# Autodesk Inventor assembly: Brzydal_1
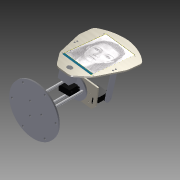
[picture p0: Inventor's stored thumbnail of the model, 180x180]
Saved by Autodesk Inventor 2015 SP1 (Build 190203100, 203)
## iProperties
Created: 2016-02
Part Number: Brzydal_1
Document SubType Name: Assembly
Designer: Rafał
Author: Rafał
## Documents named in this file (12)
- D:\Dropbox\Brzydal\Mechanika\Brzydal_1.iam
- D:\Dropbox\Brzydal\Mechanika\MG996R.ipt
- D:\Dropbox\Brzydal\Mechanika\orczyk_okragly.ipt
- D:\Dropbox\Brzydal\Mechanika\sruba_2_5.ipt
- D:\Dropbox\Brzydal\Mechanika\talerz.ipt
- D:\Dropbox\Brzydal\Mechanika\mocowanie_twarzy.ipt
- D:\Dropbox\Brzydal\Mechanika\twarz.ipt
- D:\Dropbox\Brzydal\Mechanika\podstawka dolna.ipt
- D:\Dropbox\Brzydal\Mechanika\sruba_80.ipt
- D:\Dropbox\Brzydal\Mechanika\twarz_ekran.ipt
- D:\Dropbox\Brzydal\Mechanika\sam_dol.ipt
- D:\Dropbox\Brzydal\Mechanika\kamera.ipt
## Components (29 placed, 11 different names)
1. MG996R:1 — Insert:5, Mate:21, Mate:22, Mate:23
2. orczyk_okragly:1 — Insert:5, Insert:6, Insert:7, Insert:8, Insert:9, Rotational:3
3. sruba_2_5:1 — Insert:8
4. sruba_2_5:2 — Insert:9
5. sruba_2_5:3 — Insert:7
6. sruba_2_5:4 — Insert:6
7. MG996R:2 — Insert:11, Mate:24, Mate:25, Mate:26
8. MG996R:3 — Insert:10, Mate:27, Mate:28, Mate:29
9. orczyk_okragly:2 — Insert:10, Insert:14, Insert:15, Insert:16, Insert:17, Rotational:1
10. orczyk_okragly:3 — Insert:11, Insert:12, Insert:13, Insert:18, Insert:19, Rotational:2
11. sruba_2_5:5 — Insert:15
12. sruba_2_5:6 — Insert:12
13. sruba_2_5:7 — Insert:14
14. sruba_2_5:8 — Insert:13
15. sruba_2_5:9 — Insert:17
16. sruba_2_5:10 — Insert:18
17. sruba_2_5:11 — Insert:19
18. sruba_2_5:12 — Insert:16
19. mocowanie_twarzy:1 — Rotational:2, Mate:19, Mate:20, Flush:3
20. mocowanie_twarzy:2 — Rotational:1, Flush:4
21. twarz:1 — Mate:19, Mate:20, Flush:3, Flush:4, Mate:30, Mate:31, Flush:5, Rotational:4
22. talerz:1 — Rotational:3, Mate:24, Mate:25, Mate:26, Mate:27, Mate:28, Mate:29
23. podstawka dolna:1 — Mate:21, Mate:22, Mate:23, Insert:20, Insert:21, Insert:22
24. sruba_80:1 — Insert:21
25. sruba_80:2 — Insert:20, Insert:23
26. sruba_80:3 — Insert:22
27. twarz_ekran:1 — Mate:30, Mate:31, Flush:5
28. sam_dol:1 — Insert:23
29. kamera:1 — Rotational:4
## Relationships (39: Insert 19, Mate 13, RevoluteJoint 4, Flush 3)
- Insert:5: MG996R:1 ↔ orczyk_okragly:1
- Insert:6: orczyk_okragly:1 ↔ sruba_2_5:4
- Insert:7: orczyk_okragly:1 ↔ sruba_2_5:3
- Insert:8: orczyk_okragly:1 ↔ sruba_2_5:1
- Insert:9: orczyk_okragly:1 ↔ sruba_2_5:2
- Insert:10: MG996R:3 ↔ orczyk_okragly:2
- Insert:11: MG996R:2 ↔ orczyk_okragly:3
- Insert:12: orczyk_okragly:3 ↔ sruba_2_5:6
- Insert:13: orczyk_okragly:3 ↔ sruba_2_5:8
- Insert:14: orczyk_okragly:2 ↔ sruba_2_5:7
- Insert:15: orczyk_okragly:2 ↔ sruba_2_5:5
- Insert:16: orczyk_okragly:2 ↔ sruba_2_5:12
- Insert:17: orczyk_okragly:2 ↔ sruba_2_5:9
- Insert:18: orczyk_okragly:3 ↔ sruba_2_5:10
- Insert:19: orczyk_okragly:3 ↔ sruba_2_5:11
- Rotational:1 [RevoluteJoint]: orczyk_okragly:2 ↔ mocowanie_twarzy:2
- Rotational:2 [RevoluteJoint]: orczyk_okragly:3 ↔ mocowanie_twarzy:1
- Mate:19: mocowanie_twarzy:1 ↔ twarz:1
- Mate:20: mocowanie_twarzy:1 ↔ twarz:1
- Flush:3: mocowanie_twarzy:1 ↔ twarz:1
- Flush:4: mocowanie_twarzy:2 ↔ twarz:1
- Mate:21: MG996R:1 ↔ podstawka dolna:1
- Mate:22: MG996R:1 ↔ podstawka dolna:1
- Mate:23: MG996R:1 ↔ podstawka dolna:1
- Rotational:3 [RevoluteJoint]: orczyk_okragly:1 ↔ talerz:1
- Mate:24: MG996R:2 ↔ talerz:1
- Mate:25: MG996R:2 ↔ talerz:1
- Mate:26: MG996R:2 ↔ talerz:1
- Mate:27: MG996R:3 ↔ talerz:1
- Mate:28: MG996R:3 ↔ talerz:1
- Mate:29: MG996R:3 ↔ talerz:1
- Insert:20: podstawka dolna:1 ↔ sruba_80:2
- Insert:21: podstawka dolna:1 ↔ sruba_80:1
- Insert:22: podstawka dolna:1 ↔ sruba_80:3
- Mate:30: twarz:1 ↔ twarz_ekran:1
- Mate:31: twarz:1 ↔ twarz_ekran:1
- Flush:5: twarz:1 ↔ twarz_ekran:1
- Insert:23: sruba_80:2 ↔ sam_dol:1
- Rotational:4 [RevoluteJoint]: twarz:1 ↔ kamera:1
